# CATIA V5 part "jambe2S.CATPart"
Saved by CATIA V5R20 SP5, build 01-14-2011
Part number: jambe2S
Publications: "Plan.1", "Droite.1", "Point.1", "Plan.2", "Plan.3", "Point.2", "Point.3", "Droite.2", "Droite.3", "Plan.4", "Droite.4", "Point.4", "Droite.5"
Bounding box of the stored display mesh (mm): x -400 to 0, y -1070 to -70, z 10 to 50
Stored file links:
  U:\think motion\fin\jambe2S.CATPart
  U:\think motion\fin\squelette.CATProduct
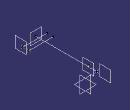
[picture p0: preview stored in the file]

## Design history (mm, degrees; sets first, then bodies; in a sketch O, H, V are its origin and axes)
External parameters (linked from other documents)
  `External.écartement jambe` = 650 mm
  `External.longueur jambe` = 1000 mm
  `External.implentation verin2` = 130 mm
Set1
  Point1: linked copy from another document
Set2
  Plane1: type Offset, RefPlane yz-plane, Offset -325 {= -`External.écartement jambe` /2}
  Line1: type PtDir, RefPoint Point1, Direction zx-plane, Start 0, End 1000 {= `External.longueur jambe`}
  Plane2: type Normal, Curve Line1, RefPoint vertex of Line1
  Plane3: type Angle, RefPlane Plane2, Direction Z axis, Angle 90
  Point2: type OnPlane, Support Plane3, RefPoint vertex of Line1, H -35, V -14, Direction (0, -1, 0)
  Point3: type OnPlane, Support Plane3, RefPoint vertex of Line1, H -135, V -14, Direction (0, -1, 0)
  Line2: type PtDir, RefPoint Point2, Direction Plane3, Start 0, End 400
  Line3: type PtDir, RefPoint Point3, Direction Plane3, Start 0, End 400
  Point4: type OnCurve, Support Line1, RefPoint Point1, Length 130 {= `External.implentation verin2`}
  Line4: type PtDir, RefPoint Point4, Direction Plane1, Start 0, End 5
  Plane4: type Normal, Curve Line4, RefPoint Point4
  Line5: type PtDir, RefPoint Point4, Direction xy-plane, Start -20, End 20
Body1 (main body)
